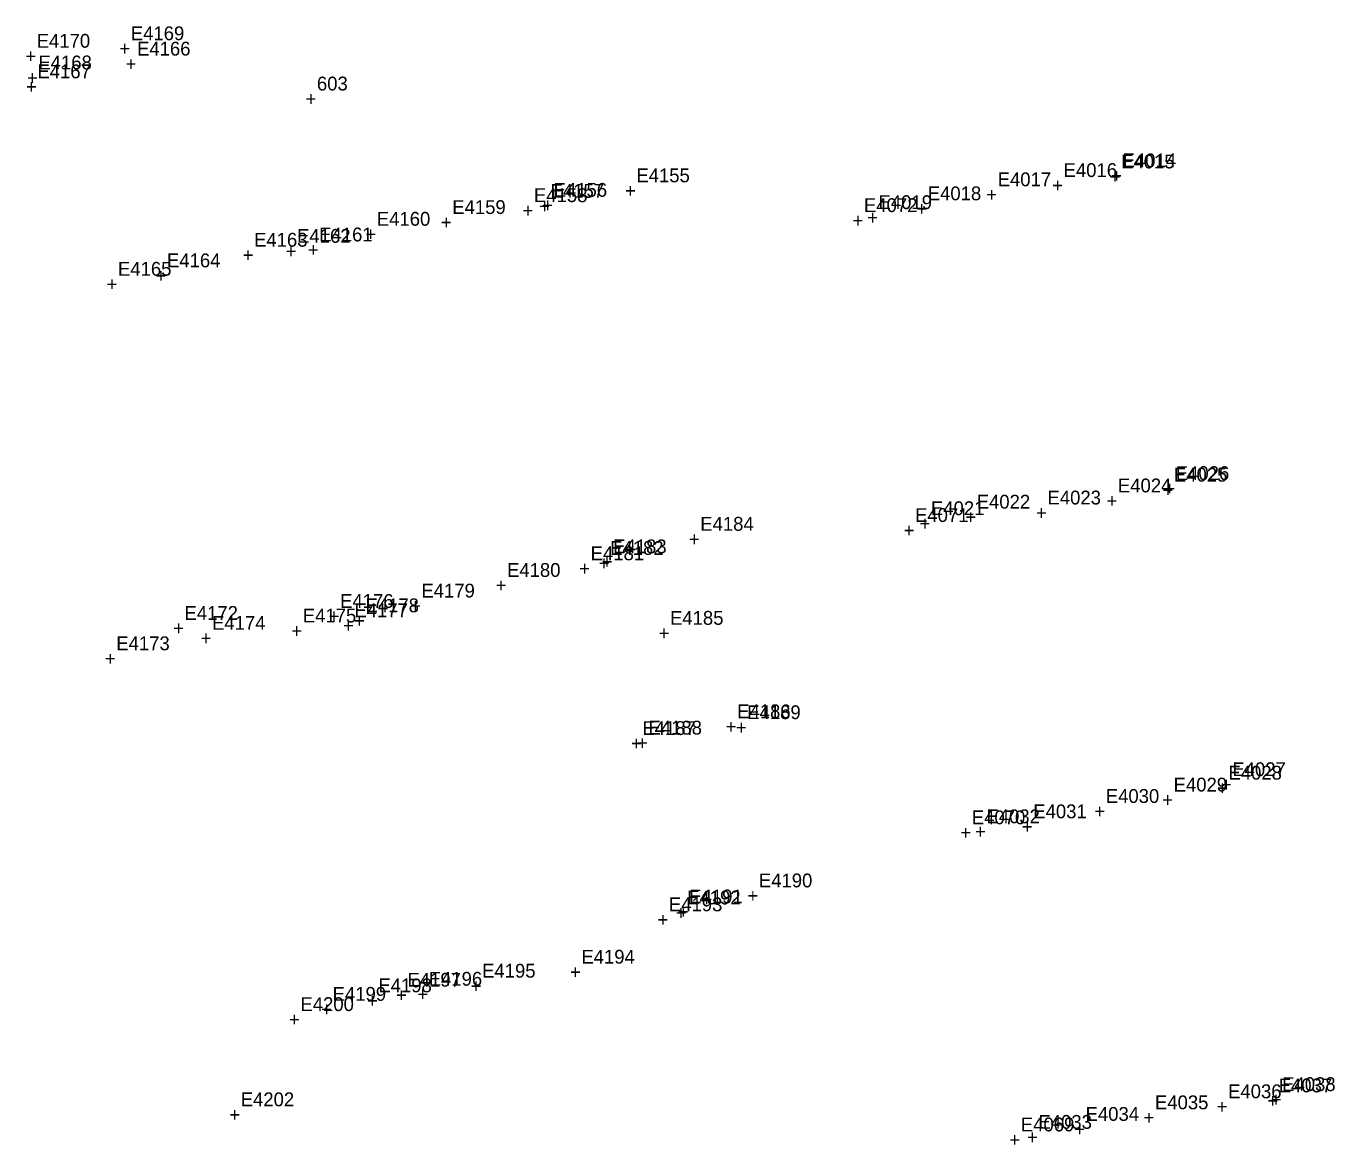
# Model space of a CAD drawing. Extents: x 1667192 to 1669644, y 336680 to 339991.
# Drawn here: x 1667213.2 to 1667449.8, y 336887.4 to 337089.7 of the extents above; entities that cross this region are included whole.
import ezdxf

# ---------------------------------------------------------------- set-up
doc = ezdxf.new("R2010")
doc.units = 0
for name, color, linetype in [('S_Control_Temp_Traverse', 7, 'Continuous'), ('S_Curb_Type_5', 7, 'Continuous'), ('S_Drainage_CB', 7, 'Continuous'), ('S_Ground_Elevation', 7, 'Continuous'), ('S_Guardrail_Beam', 7, 'Continuous'), ('S_Roadway_Edge_Pavement', 7, 'Continuous'), ('S_Roadway_Edge_TW', 7, 'Continuous'), ('S_Traffic_Sign_SinglePost', 7, 'Continuous'), ('S_Utilities_GuyWire3', 7, 'Continuous'), ('S_Utilities_Pole_Power', 7, 'Continuous'), ('S_Utilities_UG_Electrical_Line', 7, 'Continuous')]:
    doc.layers.add(name, color=color, linetype=linetype)

msp = doc.modelspace()

# ---------------------------------------------------------------- texts
at = {"layer": 'S_Control_Temp_Traverse'}
for s, p in [('603', (1667265.76, 337078.12)), ('603', (1667265.76, 337078.12)), ('603', (1667265.76, 337078.12)), ('603', (1667265.76, 337078.12)), ('603', (1667265.76, 337078.12)), ('+', (1667263.69, 337075.37)), ('+', (1667263.69, 337075.37)), ('+', (1667263.69, 337075.37)), ('+', (1667263.69, 337075.37)), ('+', (1667263.69, 337075.37))]:
    msp.add_text(s, height=2.5, dxfattribs=at).set_placement(p)
at = {"layer": 'S_Curb_Type_5'}
for s, p in [('E4156', (1667308.56, 337058.89)), ('+', (1667306.49, 337056.14)), ('E4183', (1667319.32, 336994.42)), ('+', (1667317.25, 336991.67)), ('E4191', (1667333.08, 336931.12)), ('+', (1667331.02, 336928.37))]:
    msp.add_text(s, height=2.5, dxfattribs=at).set_placement(p)
at = {"layer": 'S_Drainage_CB'}
for s, p in [('E4186', (1667341.74, 336964.59)), ('E4187', (1667324.6, 336961.56)), ('+', (1667339.68, 336961.84)), ('+', (1667322.54, 336958.81))]:
    msp.add_text(s, height=2.5, dxfattribs=at).set_placement(p)
at = {"layer": 'S_Ground_Elevation'}
for s, p in [('E4155', (1667323.52, 337061.52)), ('+', (1667321.46, 337058.77)), ('E4072', (1667364.67, 337056.13)), ('+', (1667362.61, 337053.38)), ('E4162', (1667262.17, 337050.57)), ('E4163', (1667254.39, 337049.87)), ('E4164', (1667238.65, 337046.14)), ('+', (1667252.33, 337047.12)), ('+', (1667260.11, 337047.82)), ('E4165', (1667229.79, 337044.62)), ('+', (1667227.73, 337041.87)), ('+', (1667236.59, 337043.39)), ('E4184', (1667335.07, 336998.5)), ('E4071', (1667373.9, 337000.08)), ('+', (1667371.84, 336997.33)), ('+', (1667333.01, 336995.75)), ('E4172', (1667241.82, 336982.38)), ('E4175', (1667263.21, 336981.91)), ('E4177', (1667272.53, 336982.86)), ('E4174', (1667246.79, 336980.58)), ('+', (1667270.47, 336980.11)), ('+', (1667239.76, 336979.63)), ('+', (1667244.73, 336977.83)), ('+', (1667261.14, 336979.16)), ('E4173', (1667229.48, 336976.89)), ('+', (1667227.42, 336974.14)), ('E4189', (1667343.56, 336964.43)), ('+', (1667341.5, 336961.68)), ('E4070', (1667384.16, 336945.42)), ('+', (1667382.1, 336942.67)), ('E4190', (1667345.67, 336934.01)), ('+', (1667343.6, 336931.26)), ('E4197', (1667282.12, 336916.05)), ('E4199', (1667268.6, 336913.49)), ('E4198', (1667276.87, 336915.03)), ('E4200', (1667262.78, 336911.64)), ('+', (1667274.81, 336912.28)), ('+', (1667280.06, 336913.3)), ('+', (1667260.72, 336908.89)), ('+', (1667266.54, 336910.74)), ('E4069', (1667393.03, 336889.88)), ('+', (1667390.97, 336887.13))]:
    msp.add_text(s, height=2.5, dxfattribs=at).set_placement(p)
at = {"layer": 'S_Guardrail_Beam'}
for s, p in [('E4014', (1667411.43, 337064.23)), ('+', (1667409.37, 337061.48)), ('E4019', (1667367.3, 337056.67)), ('+', (1667365.24, 337053.92)), ('E4026', (1667421.05, 337007.67)), ('+', (1667418.99, 337004.92)), ('E4021', (1667376.78, 337001.32)), ('+', (1667374.72, 336998.57)), ('E4027', (1667431.27, 336954.12)), ('+', (1667429.21, 336951.37)), ('E4032', (1667386.81, 336945.61)), ('+', (1667384.75, 336942.86)), ('E4038', (1667440.28, 336897.17)), ('+', (1667438.22, 336894.42)), ('E4033', (1667396.22, 336890.34)), ('+', (1667394.16, 336887.59))]:
    msp.add_text(s, height=2.5, dxfattribs=at).set_placement(p)
at = {"layer": 'S_Roadway_Edge_Pavement'}
for s, p in [('E4015', (1667411.16, 337064.03)), ('+', (1667409.09, 337061.28)), ('E4157', (1667308, 337058.71)), ('+', (1667305.94, 337055.96)), ('E4161', (1667266.17, 337050.83)), ('+', (1667264.11, 337048.08)), ('E4025', (1667420.7, 337007.38)), ('+', (1667418.64, 337004.63)), ('E4182', (1667318.77, 336994.14)), ('+', (1667316.71, 336991.39)), ('E4178', (1667274.54, 336983.75)), ('+', (1667272.47, 336981)), ('E4188', (1667325.71, 336961.64)), ('+', (1667323.65, 336958.89)), ('E4028', (1667430.57, 336953.49)), ('+', (1667428.51, 336950.74)), ('E4192', (1667332.69, 336930.92)), ('+', (1667330.63, 336928.17)), ('E4196', (1667285.97, 336916.22)), ('+', (1667283.91, 336913.47)), ('E4037', (1667439.65, 336896.94)), ('+', (1667437.59, 336894.19))]:
    msp.add_text(s, height=2.5, dxfattribs=at).set_placement(p)
at = {"layer": 'S_Roadway_Edge_TW'}
for s, p in [('E4016', (1667400.76, 337062.47)), ('E4017', (1667388.84, 337060.8)), ('E4158', (1667305, 337057.93)), ('E4018', (1667376.2, 337058.26)), ('+', (1667386.78, 337058.05)), ('+', (1667398.7, 337059.72)), ('E4159', (1667290.23, 337055.78)), ('+', (1667374.14, 337055.51)), ('E4160', (1667276.59, 337053.66)), ('+', (1667302.93, 337055.18)), ('+', (1667274.53, 337050.91)), ('+', (1667288.17, 337053.03)), ('E4024', (1667410.58, 337005.44)), ('E4023', (1667397.85, 337003.25)), ('E4022', (1667385.05, 337002.5)), ('+', (1667408.52, 337002.69)), ('+', (1667382.99, 336999.75)), ('+', (1667395.79, 337000.5)), ('E4181', (1667315.25, 336993.17)), ('E4180', (1667300.13, 336990.15)), ('+', (1667313.19, 336990.42)), ('E4179', (1667284.65, 336986.42)), ('+', (1667298.07, 336987.4)), ('+', (1667282.59, 336983.67)), ('E4029', (1667420.66, 336951.34)), ('E4030', (1667408.39, 336949.28)), ('E4031', (1667395.28, 336946.5)), ('+', (1667418.59, 336948.59)), ('+', (1667406.33, 336946.53)), ('+', (1667393.22, 336943.75)), ('E4193', (1667329.4, 336929.68)), ('+', (1667327.33, 336926.93)), ('E4194', (1667313.57, 336920.21)), ('E4195', (1667295.62, 336917.68)), ('+', (1667311.51, 336917.46)), ('+', (1667293.56, 336914.93)), ('E4036', (1667430.5, 336895.87)), ('E4034', (1667404.74, 336891.78)), ('E4035', (1667417.28, 336893.88)), ('+', (1667428.44, 336893.12)), ('+', (1667415.21, 336891.13)), ('+', (1667402.68, 336889.03))]:
    msp.add_text(s, height=2.5, dxfattribs=at).set_placement(p)
at = {"layer": 'S_Traffic_Sign_SinglePost'}
for s, p in [('E4176', (1667269.95, 336984.55)), ('+', (1667267.89, 336981.8)), ('E4185', (1667329.6, 336981.49)), ('+', (1667327.54, 336978.74))]:
    msp.add_text(s, height=2.5, dxfattribs=at).set_placement(p)
at = {"layer": 'S_Utilities_GuyWire3'}
for s, p in [('E4170', (1667215.09, 337085.85)), ('+', (1667213.03, 337083.1)), ('E4168', (1667215.4, 337081.93)), ('+', (1667213.34, 337079.18)), ('E4202', (1667251.98, 336894.42)), ('+', (1667249.92, 336891.67))]:
    msp.add_text(s, height=2.5, dxfattribs=at).set_placement(p)
at = {"layer": 'S_Utilities_Pole_Power'}
for s, p in [('E4169', (1667232.11, 337087.21)), ('+', (1667230.05, 337084.46)), ('E4166', (1667233.23, 337084.43)), ('+', (1667231.17, 337081.68))]:
    msp.add_text(s, height=2.5, dxfattribs=at).set_placement(p)
at = {"layer": 'S_Utilities_UG_Electrical_Line'}
for s, p in [('E4167', (1667215.22, 337080.32)), ('+', (1667213.16, 337077.57))]:
    msp.add_text(s, height=2.5, dxfattribs=at).set_placement(p)

doc.saveas('drawing.dxf')
